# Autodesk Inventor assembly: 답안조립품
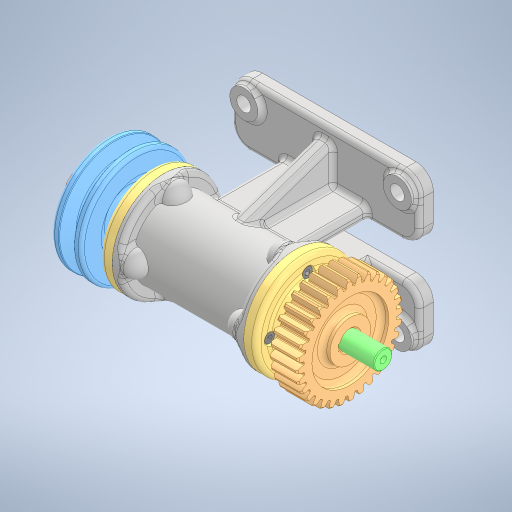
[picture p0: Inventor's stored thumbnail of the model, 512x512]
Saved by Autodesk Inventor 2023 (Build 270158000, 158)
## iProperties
Created: 2026-06
Part Number: 답안조립품
Document SubType Name: Assembly
Designer: home
Author: home
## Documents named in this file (16)
- C:\Users\home\Desktop\760603V1006\답안조립품.iam
- C:\Users\home\Desktop\760603V1006\본체.ipt
- C:\Users\home\Desktop\760403V1014\6각 구멍붙이 볼트 M4x8.ipt
- C:\Users\home\Desktop\760403V1014\6각 너트 M12x1.ipt
- C:\Users\home\Desktop\760403V1014\V 벨트 풀리.ipt
- C:\Users\home\Desktop\760403V1014\깊은 홈 볼 베어링 6904.ipt
- C:\Users\home\Desktop\760403V1014\스퍼 기어.ipt
- C:\Users\home\Desktop\760403V1014\스프링 와셔 M12.ipt
- C:\Users\home\Desktop\760403V1014\오일 실 20 35 8.ipt
- C:\Users\home\Desktop\760403V1014\축.ipt
- C:\Users\home\Desktop\760403V1014\커버.ipt
- C:\Users\home\Desktop\760403V1014\평 와셔 M12.ipt
- C:\Users\home\Desktop\760403V1014\평행 키 4x4x14.ipt
- C:\Users\home\Desktop\760403V1014\커버_MIR.ipt
- C:\Users\home\Desktop\760403V1014\6각 구멍붙이 볼트 M4x8_MIR.ipt
- C:\Users\home\Desktop\760403V1014\오일 실 20 35 8_MIR.ipt
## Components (10 placed, 4 different names)
1. 6각 너트 M12x1:1 — 각도:10
2. V 벨트 풀리:1
3. 6각 구멍붙이 볼트 M4x8_MIR:1 — 각도:8
4. 6각 구멍붙이 볼트 M4x8_MIR:2 — 각도:6
5. 6각 구멍붙이 볼트 M4x8_MIR:3 — 각도:7
6. 6각 구멍붙이 볼트 M4x8_MIR:4 — 각도:9
7. 6각 구멍붙이 볼트 M4x8:1 — 각도:1
8. 6각 구멍붙이 볼트 M4x8:2
9. 6각 구멍붙이 볼트 M4x8:3
10. 6각 구멍붙이 볼트 M4x8:4
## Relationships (6: Angle 6)
- 각도:1 [Angle]: 6각 구멍붙이 볼트 M4x8:1
- 각도:6 [Angle]: 6각 구멍붙이 볼트 M4x8_MIR:2
- 각도:7 [Angle]: 6각 구멍붙이 볼트 M4x8_MIR:3
- 각도:8 [Angle]: 6각 구멍붙이 볼트 M4x8_MIR:1
- 각도:9 [Angle]: 6각 구멍붙이 볼트 M4x8_MIR:4
- 각도:10 [Angle]: 6각 너트 M12x1:1
